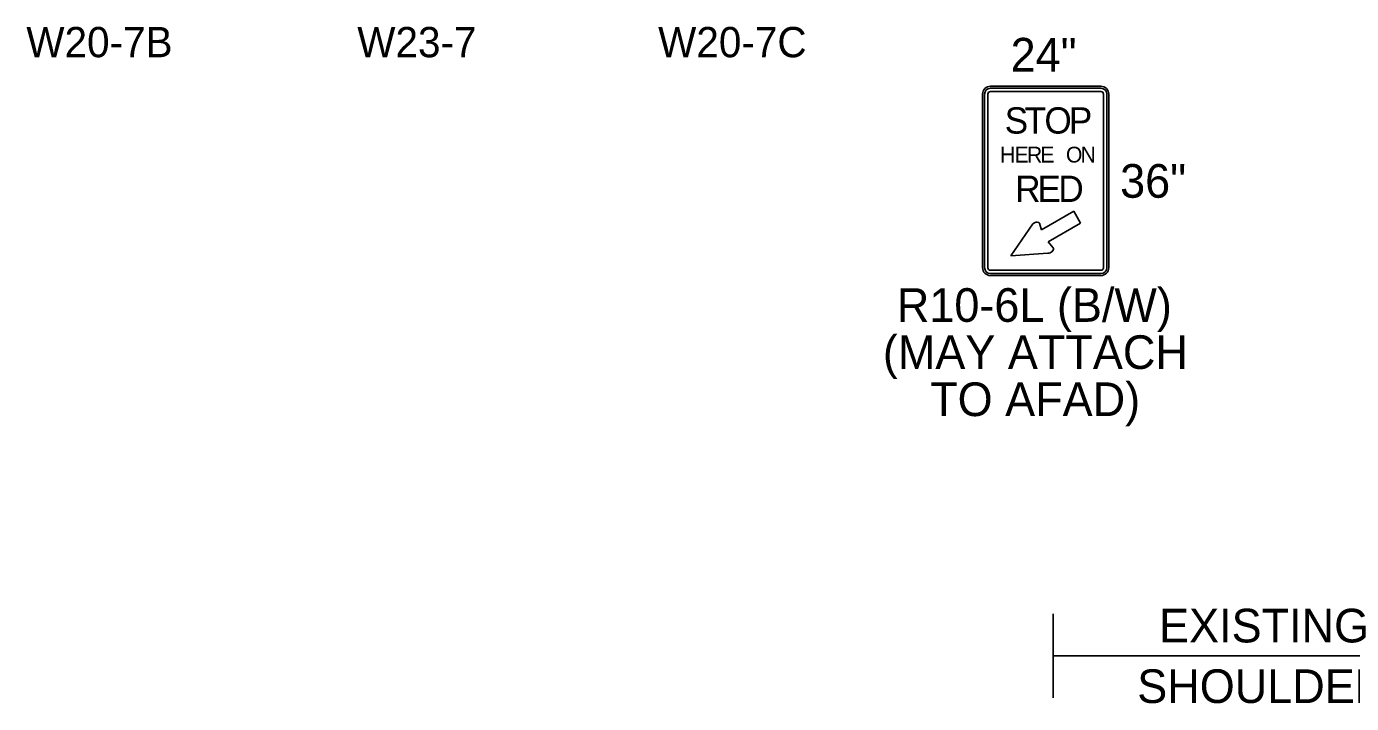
# Model space of a CAD drawing. Extents: x 99999.1 to 100095.7, y 99995 to 100010.7.
# Drawn here: x 100001.85 to 100005, y 100003.112 to 100004.722 of the extents above; entities that cross this region are included whole.
import ezdxf

# ---------------------------------------------------------------- set-up
doc = ezdxf.new("R2010")
doc.units = 0
doc.layers.add('TR_SN_ConstructionSigns', color=7, linetype='Continuous')
doc.layers.add('TR_WZ_WorkZoneDetails', color=7, linetype='Continuous')

msp = doc.modelspace()

# ---------------------------------------------------------------- linework, layer by layer
at = {"layer": 'TR_SN_ConstructionSigns'}
for p, q in [((100004.4041, 100004.5796), (100004.1416, 100004.5796)), ((100004.1416, 100004.5796), (100004.4041, 100004.5796)), ((100004.4041, 100004.5796), (100004.1416, 100004.5796)), ((100004.4041, 100004.5749), (100004.1416, 100004.5749)), ((100004.1416, 100004.5671), (100004.4041, 100004.5671)), ((100004.1229, 100004.5609), (100004.1229, 100004.1484)), ((100004.1229, 100004.1484), (100004.1229, 100004.5609)), ((100004.1229, 100004.5609), (100004.1229, 100004.1484)), ((100004.1276, 100004.5609), (100004.1276, 100004.1484)), ((100004.1354, 100004.1484), (100004.1354, 100004.5609)), ((100004.4104, 100004.5609), (100004.4104, 100004.1484)), ((100004.4182, 100004.1484), (100004.4182, 100004.5609)), ((100004.4229, 100004.1484), (100004.4229, 100004.5609)), ((100004.4229, 100004.5609), (100004.4229, 100004.1484)), ((100004.4229, 100004.1484), (100004.4229, 100004.5609)), ((100004.3396, 100004.2827), (100004.263, 100004.2385)), ((100004.356, 100004.2543), (100004.3396, 100004.2827)), ((100004.2424, 100004.2523), (100004.1898, 100004.1766)), ((100004.263, 100004.2385), (100004.2592, 100004.2511)), ((100004.2786, 100004.2096), (100004.356, 100004.2543)), ((100004.2909, 100004.1959), (100004.2786, 100004.2096)), ((100004.1898, 100004.1766), (100004.2776, 100004.1827)), ((100004.4041, 100004.1421), (100004.1416, 100004.1421)), ((100004.1416, 100004.1343), (100004.4041, 100004.1343)), ((100004.1416, 100004.1296), (100004.4041, 100004.1296)), ((100004.4041, 100004.1296), (100004.1416, 100004.1296)), ((100004.1416, 100004.1296), (100004.4041, 100004.1296))]:
    msp.add_line(p, q, dxfattribs=at)
for centre, radius, start, end in [((100004.1416, 100004.5609), 0.0187, 90, 180), ((100004.1416, 100004.5609), 0.0187, 90, 180), ((100004.1416, 100004.5609), 0.0187, 90, 180), ((100004.1416, 100004.5609), 0.0141, 90, 180), ((100004.1416, 100004.5609), 0.00625, 90, 180), ((100004.4041, 100004.5609), 0.0187, 0, 90), ((100004.4041, 100004.5609), 0.0187, 0, 90), ((100004.4041, 100004.5609), 0.0187, 0, 90), ((100004.4041, 100004.5609), 0.0141, 0, 90), ((100004.4041, 100004.5609), 0.00625, 0, 90), ((100004.1416, 100004.1484), 0.0187, 180, 270), ((100004.1416, 100004.1484), 0.0187, 180, 270), ((100004.1416, 100004.1484), 0.0187, 180, 270), ((100004.1416, 100004.1484), 0.0141, 180, 270), ((100004.1416, 100004.1484), 0.00625, 180, 270), ((100004.4041, 100004.1484), 0.0187, 270, 0), ((100004.4041, 100004.1484), 0.0187, 270, 0), ((100004.4041, 100004.1484), 0.0187, 270, 0), ((100004.4041, 100004.1484), 0.0141, 270, 0), ((100004.4041, 100004.1484), 0.00625, 270, 0)]:
    msp.add_arc(centre, radius, start, end, dxfattribs=at)
for centre, major_axis, start_param, end_param in [((100004.2492, 100004.248), (0.00934, 0.00539), 5.977036, 8.198856), ((100004.2816, 100004.1909), (-0.00913, -0.00527), 0.771965, 3.092601)]:
    msp.add_ellipse(centre, major_axis=major_axis, ratio=0.700347, start_param=start_param, end_param=end_param, dxfattribs=at)
at = {"layer": 'TR_WZ_WorkZoneDetails'}
for p, q in [((100004.2907, 100003.1255), (100004.2907, 100003.3255)), ((100004.2907, 100003.2255), (100005.2907, 100003.2255))]:
    msp.add_line(p, q, dxfattribs=at)

# ---------------------------------------------------------------- texts
at = {"layer": 'TR_SN_ConstructionSigns'}
for s, height, p in [('W20-7B', 0.072, (100001.8493, 100004.6486)), ('W23-7', 0.072, (100002.6361, 100004.6486)), ('W20-7C', 0.072, (100003.3514, 100004.6486)), ('24"', 0.08, (100004.1895, 100004.6146)), ('36"', 0.08, (100004.4498, 100004.3146)), ('R10-6L (B/W)', 0.08, (100003.919, 100004.0196)), ('(MAY ATTACH', 0.08, (100003.8858, 100003.9076)), ('TO AFAD)', 0.08, (100003.9982, 100003.7956))]:
    msp.add_text(s, height=height, rotation=360, dxfattribs=at).set_placement(p)
for s, height, p in [('S', 0.0625, (100004.1754, 100004.4671)), ('T', 0.0625, (100004.2229, 100004.4671)), ('O', 0.0625, (100004.2698, 100004.4671)), ('P', 0.0625, (100004.3279, 100004.4671)), ('H', 0.0375, (100004.1643, 100004.3984)), ('E', 0.0375, (100004.1988, 100004.3984)), ('R', 0.0375, (100004.2284, 100004.3984)), ('E', 0.0375, (100004.2603, 100004.3984)), ('O', 0.0375, (100004.3211, 100004.3984)), ('N', 0.0375, (100004.3559, 100004.3984)), ('R', 0.0625, (100004.2004, 100004.3046)), ('E', 0.0625, (100004.2535, 100004.3046)), ('D', 0.0625, (100004.3029, 100004.3046))]:
    msp.add_text(s, height=height, dxfattribs=at).set_placement(p)
at = {"layer": 'TR_WZ_WorkZoneDetails'}
for s, p in [('EXISTING', (100004.5424, 100003.2575)), ('SHOULDER', (100004.4905, 100003.1135))]:
    msp.add_text(s, height=0.08, rotation=360, dxfattribs=at).set_placement(p)

doc.saveas('drawing.dxf')
